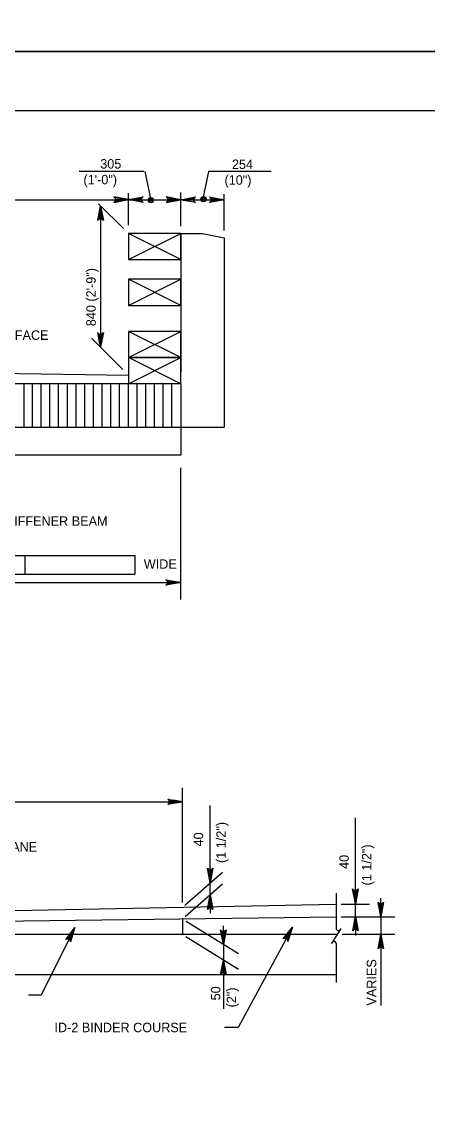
# Model space of a CAD drawing. Extents: x -8 to 75, y -110 to 0.
# Drawn here: x 9.71 to 14.86, y -79.61 to -65.62 of the extents above; entities that cross this region are included whole.
import ezdxf

# ---------------------------------------------------------------- set-up
doc = ezdxf.new("R2010")
doc.units = 0
for name, color, linetype in [('1', 7, 'Continuous'), ('2', 7, 'Continuous'), ('3', 7, 'Continuous'), ('4', 7, 'Continuous'), ('63', 7, 'Continuous'), ('7', 7, 'Continuous')]:
    doc.layers.add(name, color=color, linetype=linetype)

msp = doc.modelspace()

# ---------------------------------------------------------------- linework, layer by layer
at = {"layer": '1'}
msp.add_lwpolyline([(1.75, -87.25), (33.25, -87.25), (33.25, -66.75), (1.75, -66.75)], close=True, dxfattribs=at)
at = {"layer": '2'}
for p, q in [((13.698, -76.681), (13.698, -77.128)), ((13.698, -77.322), (13.698, -77.814))]:
    msp.add_line(p, q, dxfattribs=at)
msp.add_lwpolyline([(13.751, -77.142), (13.758, -77.13), (13.637, -77.323), (13.646, -77.31)], dxfattribs=at)
for centre, start, end in [((13.726, -77.128), 180, 330), ((13.67, -77.325), 5.3286, 147.8672)]:
    msp.add_arc(centre, 0.0284, start, end, dxfattribs=at)
at = {"layer": '3'}
for p, q in [((11.061, -68.641), (11.724, -68.31)), ((11.724, -68.641), (11.061, -68.31)), ((11.724, -68.31), (11.061, -68.31)), ((11.061, -68.31), (11.061, -68.641)), ((11.724, -68.31), (11.724, -70.068)), ((11.724, -68.641), (11.724, -68.31)), ((11.724, -68.31), (12, -68.31)), ((12, -68.31), (12.277, -68.365)), ((12.277, -68.365), (12.277, -70.769)), ((11.061, -68.641), (11.724, -68.641)), ((11.061, -68.89), (11.061, -69.222)), ((11.724, -69.222), (11.061, -68.89)), ((11.061, -69.222), (11.724, -68.89)), ((11.724, -68.89), (11.061, -68.89)), ((11.724, -69.222), (11.724, -68.89)), ((11.061, -69.222), (11.724, -69.222)), ((11.061, -69.885), (11.724, -69.553)), ((11.724, -69.885), (11.061, -69.553)), ((11.061, -69.553), (11.061, -69.885)), ((11.724, -69.553), (11.061, -69.553)), ((11.724, -69.885), (11.724, -69.553)), ((11.724, -69.885), (11.061, -69.885)), ((11.724, -70.217), (11.061, -69.885)), ((11.061, -70.217), (11.724, -69.885)), ((11.061, -69.885), (11.724, -69.885)), ((11.061, -69.885), (11.061, -70.217)), ((11.724, -70.217), (11.724, -69.885)), ((7.743, -70.056), (11.061, -70.106)), ((11.724, -70.217), (3.762, -70.217)), ((11.724, -70.217), (11.724, -70.769)), ((3.762, -70.769), (11.724, -70.769)), ((11.724, -70.769), (11.724, -71.124)), ((11.724, -70.769), (12.277, -70.769)), ((11.724, -71.124), (3.762, -71.124)), ((4.364, -77.008), (13.698, -76.821)), ((4.364, -77.106), (13.698, -76.982)), ((11.746, -77.008), (11.746, -77.204)), ((4.425, -77.204), (13.712, -77.204)), ((5.133, -77.716), (13.698, -77.716))]:
    msp.add_line(p, q, dxfattribs=at)
at = {"layer": '4'}
for p, q in [((11.255, -67.523), (10.434, -67.523)), ((11.267, -67.523), (11.344, -67.886)), ((12.077, -67.523), (12, -67.886)), ((12.872, -67.523), (12.077, -67.523)), ((11.061, -68.204), (11.061, -67.797)), ((11.724, -68.216), (11.724, -67.79)), ((12.277, -68.27), (12.277, -67.81)), ((3.21, -67.88), (12.277, -67.88)), ((10.996, -68.245), (10.682, -67.931)), ((10.707, -67.956), (10.707, -69.753)), ((10.99, -70.035), (10.591, -69.637)), ((11.724, -72.954), (11.724, -71.284)), ((9.443, -72.395), (11.143, -72.395)), ((9.745, -72.395), (9.745, -72.632)), ((11.143, -72.395), (11.143, -72.632)), ((9.443, -72.632), (11.143, -72.632)), ((3.762, -72.739), (11.724, -72.739)), ((11.746, -76.488), (11.746, -75.344)), ((4.364, -75.522), (11.746, -75.522)), ((12.097, -76.433), (12.097, -75.568)), ((13.943, -76.703), (13.943, -75.727)), ((11.746, -76.799), (11.746, -76.48)), ((11.778, -76.833), (12.255, -76.414)), ((11.782, -76.977), (12.254, -76.562)), ((12.097, -76.699), (12.097, -76.551)), ((14.264, -76.864), (14.264, -76.745)), ((12.097, -76.817), (12.097, -76.935)), ((13.759, -76.821), (14.12, -76.821)), ((13.943, -76.982), (13.943, -76.821)), ((11.792, -77.036), (12.456, -77.449)), ((13.759, -76.982), (14.441, -76.982)), ((13.759, -76.982), (14.12, -76.982)), ((14.264, -76.982), (14.264, -77.204)), ((12.265, -77.216), (12.265, -77.097)), ((13.773, -77.204), (14.441, -77.204)), ((13.943, -77.1), (13.943, -77.218)), ((11.789, -77.231), (12.456, -77.646)), ((12.265, -77.334), (12.265, -77.531)), ((14.264, -77.323), (14.264, -78.11)), ((12.265, -77.649), (12.265, -78.151)), ((9.954, -77.975), (9.792, -77.975)), ((12.454, -78.387), (12.28, -78.387))]:
    msp.add_line(p, q, dxfattribs=at)
for points in [[(10.707, -67.956), (10.742, -68.143), (10.732, -68.128), (10.72, -68.121), (10.707, -68.119), (10.695, -68.121), (10.682, -68.128), (10.672, -68.143), (10.707, -67.956), (10.682, -68.128), (10.695, -68.121), (10.707, -67.956), (10.707, -68.119), (10.72, -68.121), (10.707, -67.956), (10.732, -68.128)], [(11.061, -67.879), (10.874, -67.844), (10.889, -67.854), (10.896, -67.867), (10.898, -67.879), (10.896, -67.892), (10.889, -67.904), (10.874, -67.914), (11.061, -67.879), (10.889, -67.904), (10.896, -67.892), (11.061, -67.879), (10.898, -67.879), (10.896, -67.867), (11.061, -67.879), (10.889, -67.854)], [(11.061, -67.879), (11.247, -67.844), (11.233, -67.854), (11.225, -67.867), (11.223, -67.879), (11.225, -67.892), (11.233, -67.904), (11.247, -67.914), (11.061, -67.879), (11.233, -67.904), (11.225, -67.892), (11.061, -67.879), (11.223, -67.879), (11.225, -67.867), (11.061, -67.879), (11.233, -67.854)], [(11.724, -67.88), (11.538, -67.845), (11.552, -67.855), (11.56, -67.867), (11.562, -67.88), (11.56, -67.892), (11.552, -67.905), (11.538, -67.915), (11.724, -67.88), (11.552, -67.905), (11.56, -67.892), (11.724, -67.88), (11.562, -67.88), (11.56, -67.867), (11.724, -67.88), (11.552, -67.855)], [(11.724, -67.88), (11.911, -67.845), (11.897, -67.855), (11.889, -67.867), (11.887, -67.88), (11.889, -67.892), (11.897, -67.905), (11.911, -67.915), (11.724, -67.88), (11.897, -67.905), (11.889, -67.892), (11.724, -67.88), (11.887, -67.88), (11.889, -67.867), (11.724, -67.88), (11.897, -67.855)], [(12.277, -67.88), (12.09, -67.915), (12.104, -67.905), (12.112, -67.892), (12.114, -67.88), (12.112, -67.867), (12.104, -67.855), (12.09, -67.845), (12.277, -67.88), (12.104, -67.855), (12.112, -67.867), (12.277, -67.88), (12.114, -67.88), (12.112, -67.892), (12.277, -67.88), (12.104, -67.905)], [(10.707, -69.753), (10.672, -69.566), (10.682, -69.581), (10.695, -69.588), (10.707, -69.59), (10.72, -69.588), (10.732, -69.581), (10.742, -69.566), (10.707, -69.753), (10.732, -69.581), (10.72, -69.588), (10.707, -69.753), (10.707, -69.59), (10.695, -69.588), (10.707, -69.753), (10.682, -69.581)], [(11.724, -72.739), (11.537, -72.774), (11.552, -72.764), (11.559, -72.752), (11.561, -72.739), (11.559, -72.727), (11.552, -72.714), (11.537, -72.704), (11.724, -72.739), (11.552, -72.714), (11.559, -72.727), (11.724, -72.739), (11.561, -72.739), (11.559, -72.752), (11.724, -72.739), (11.552, -72.764)], [(11.746, -75.522), (11.56, -75.557), (11.574, -75.547), (11.582, -75.534), (11.584, -75.522), (11.582, -75.509), (11.574, -75.497), (11.56, -75.487), (11.746, -75.522), (11.574, -75.497), (11.582, -75.509), (11.746, -75.522), (11.584, -75.522), (11.582, -75.534), (11.746, -75.522), (11.574, -75.547)], [(12.097, -76.55), (12.062, -76.364), (12.072, -76.378), (12.084, -76.386), (12.097, -76.388), (12.109, -76.386), (12.122, -76.378), (12.132, -76.364), (12.097, -76.55), (12.122, -76.378), (12.109, -76.386), (12.097, -76.55), (12.097, -76.388), (12.084, -76.386), (12.097, -76.55), (12.072, -76.378)], [(13.942, -76.813), (13.907, -76.627), (13.917, -76.641), (13.929, -76.649), (13.942, -76.651), (13.954, -76.649), (13.967, -76.641), (13.977, -76.627), (13.942, -76.813), (13.967, -76.641), (13.954, -76.649), (13.942, -76.813), (13.942, -76.651), (13.929, -76.649), (13.942, -76.813), (13.917, -76.641)], [(12.098, -76.704), (12.133, -76.891), (12.123, -76.876), (12.11, -76.869), (12.098, -76.867), (12.085, -76.869), (12.073, -76.876), (12.063, -76.891), (12.098, -76.704), (12.073, -76.876), (12.085, -76.869), (12.098, -76.704), (12.098, -76.867), (12.11, -76.869), (12.098, -76.704), (12.123, -76.876)], [(14.264, -76.982), (14.229, -76.795), (14.239, -76.809), (14.251, -76.817), (14.264, -76.819), (14.276, -76.817), (14.289, -76.809), (14.299, -76.795), (14.264, -76.982), (14.289, -76.809), (14.276, -76.817), (14.264, -76.982), (14.264, -76.819), (14.251, -76.817), (14.264, -76.982), (14.239, -76.809)], [(13.943, -76.974), (13.978, -77.16), (13.968, -77.146), (13.956, -77.139), (13.943, -77.136), (13.931, -77.139), (13.918, -77.146), (13.908, -77.16), (13.943, -76.974), (13.918, -77.146), (13.931, -77.139), (13.943, -76.974), (13.943, -77.136), (13.956, -77.139), (13.943, -76.974), (13.968, -77.146)], [(10.378, -77.119), (9.954, -77.975)], [(10.378, -77.119), (10.326, -77.301), (10.324, -77.284), (10.316, -77.272), (10.306, -77.264), (10.294, -77.261), (10.279, -77.262), (10.264, -77.27), (10.378, -77.119), (10.279, -77.262), (10.294, -77.261), (10.378, -77.119), (10.306, -77.264), (10.316, -77.272), (10.378, -77.119), (10.324, -77.284)], [(12.265, -77.334), (12.23, -77.147), (12.24, -77.162), (12.252, -77.169), (12.265, -77.171), (12.277, -77.169), (12.29, -77.162), (12.3, -77.147), (12.265, -77.334), (12.29, -77.162), (12.277, -77.169), (12.265, -77.334), (12.265, -77.171), (12.252, -77.169), (12.265, -77.334), (12.24, -77.162)], [(13.144, -77.114), (12.454, -78.387)], [(13.144, -77.114), (13.086, -77.295), (13.084, -77.277), (13.076, -77.265), (13.066, -77.257), (13.054, -77.253), (13.04, -77.253), (13.024, -77.261), (13.144, -77.114), (13.04, -77.253), (13.054, -77.253), (13.144, -77.114), (13.066, -77.257), (13.076, -77.265), (13.144, -77.114), (13.084, -77.277)], [(14.264, -77.203), (14.299, -77.389), (14.289, -77.375), (14.276, -77.367), (14.264, -77.365), (14.251, -77.367), (14.239, -77.375), (14.229, -77.389), (14.264, -77.203), (14.239, -77.375), (14.251, -77.367), (14.264, -77.203), (14.264, -77.365), (14.276, -77.367), (14.264, -77.203), (14.289, -77.375)], [(12.265, -77.531), (12.3, -77.717), (12.29, -77.703), (12.277, -77.695), (12.265, -77.693), (12.252, -77.695), (12.24, -77.703), (12.23, -77.717), (12.265, -77.531), (12.24, -77.703), (12.252, -77.695), (12.265, -77.531), (12.265, -77.693), (12.277, -77.695), (12.265, -77.531), (12.29, -77.703)]]:
    msp.add_lwpolyline(points, dxfattribs=at)
for points in [[(10.689, -68.065), (10.725, -68.065), (10.707, -67.956)], [(10.725, -69.644), (10.689, -69.644), (10.707, -69.753)], [(11.628, -75.502), (11.628, -75.541), (11.746, -75.522)], [(12.077, -76.433), (12.117, -76.433), (12.097, -76.551)], [(12.077, -76.817), (12.117, -76.817), (12.097, -76.699)], [(13.923, -76.703), (13.963, -76.703), (13.943, -76.821)], [(14.244, -76.864), (14.284, -76.864), (14.264, -76.982)], [(13.923, -77.1), (13.963, -77.1), (13.943, -76.982)], [(10.378, -77.119), (10.375, -77.122), (10.377, -77.123)], [(13.144, -77.114), (13.14, -77.118), (13.143, -77.119)], [(14.244, -77.323), (14.284, -77.323), (14.264, -77.204)], [(12.245, -77.216), (12.285, -77.216), (12.265, -77.334)], [(12.245, -77.649), (12.285, -77.649), (12.265, -77.531)]]:
    msp.add_lwpolyline(points, close=True, dxfattribs=at)
for centre, radius in [((11.344, -67.886), 0.0333), ((11.344, -67.886), 0.0167), ((12.013, -67.873), 0.0333), ((12.013, -67.873), 0.0167)]:
    msp.add_circle(centre, radius, dxfattribs=at)
at = {"layer": '63'}
for points in [[(0, -66), (34, -66), (34, -44), (0, -44)], [(0, -88), (34, -88), (34, -66), (0, -66)]]:
    msp.add_lwpolyline(points, close=True, dxfattribs=at)
at = {"layer": '7'}
for p, q in [((9.733, -70.217), (9.733, -70.769)), ((9.843, -70.769), (9.843, -70.217)), ((9.953, -70.769), (9.953, -70.217)), ((10.064, -70.769), (10.064, -70.217)), ((10.174, -70.769), (10.174, -70.217)), ((10.285, -70.769), (10.285, -70.217)), ((10.396, -70.769), (10.396, -70.217)), ((10.506, -70.769), (10.506, -70.217)), ((10.617, -70.769), (10.617, -70.217)), ((10.727, -70.769), (10.727, -70.217)), ((10.838, -70.769), (10.838, -70.217)), ((10.948, -70.769), (10.948, -70.217)), ((11.059, -70.769), (11.059, -70.217)), ((11.169, -70.769), (11.169, -70.217)), ((11.28, -70.769), (11.28, -70.217)), ((11.39, -70.769), (11.39, -70.217)), ((11.501, -70.769), (11.501, -70.217)), ((11.611, -70.769), (11.611, -70.217))]:
    msp.add_line(p, q, dxfattribs=at)

# ---------------------------------------------------------------- texts
at = {"layer": '4'}
for s, p in [('305', (10.702, -67.485)), ('254', (12.374, -67.49)), ('(1\'-0")', (10.489, -67.685)), ('(10")', (12.28, -67.69)), ('BIT. WRG. SURFACE', (8.458, -69.659)), ('GLULAM STIFFENER BEAM', (8.7, -72.019)), ('WIDE', (11.255, -72.565)), ('WATERPROOF MEMBRANE', (7.78, -76.154)), ('ID-2 BINDER COURSE', (10.121, -78.447))]:
    msp.add_text(s, height=0.12, dxfattribs=at).set_placement(p)
for s, p in [('840 (2\'-9")', (10.645, -69.486)), ('(1 1/2")', (12.296, -76.299)), ('40', (12.009, -76.089)), ('(1 1/2")', (14.145, -76.584)), ('40', (13.858, -76.374)), ('VARIES', (14.206, -78.109)), ('50', (12.227, -78.043)), ('(2")', (12.427, -78.132))]:
    msp.add_text(s, height=0.12, rotation=90, dxfattribs=at).set_placement(p)

doc.saveas('drawing.dxf')
